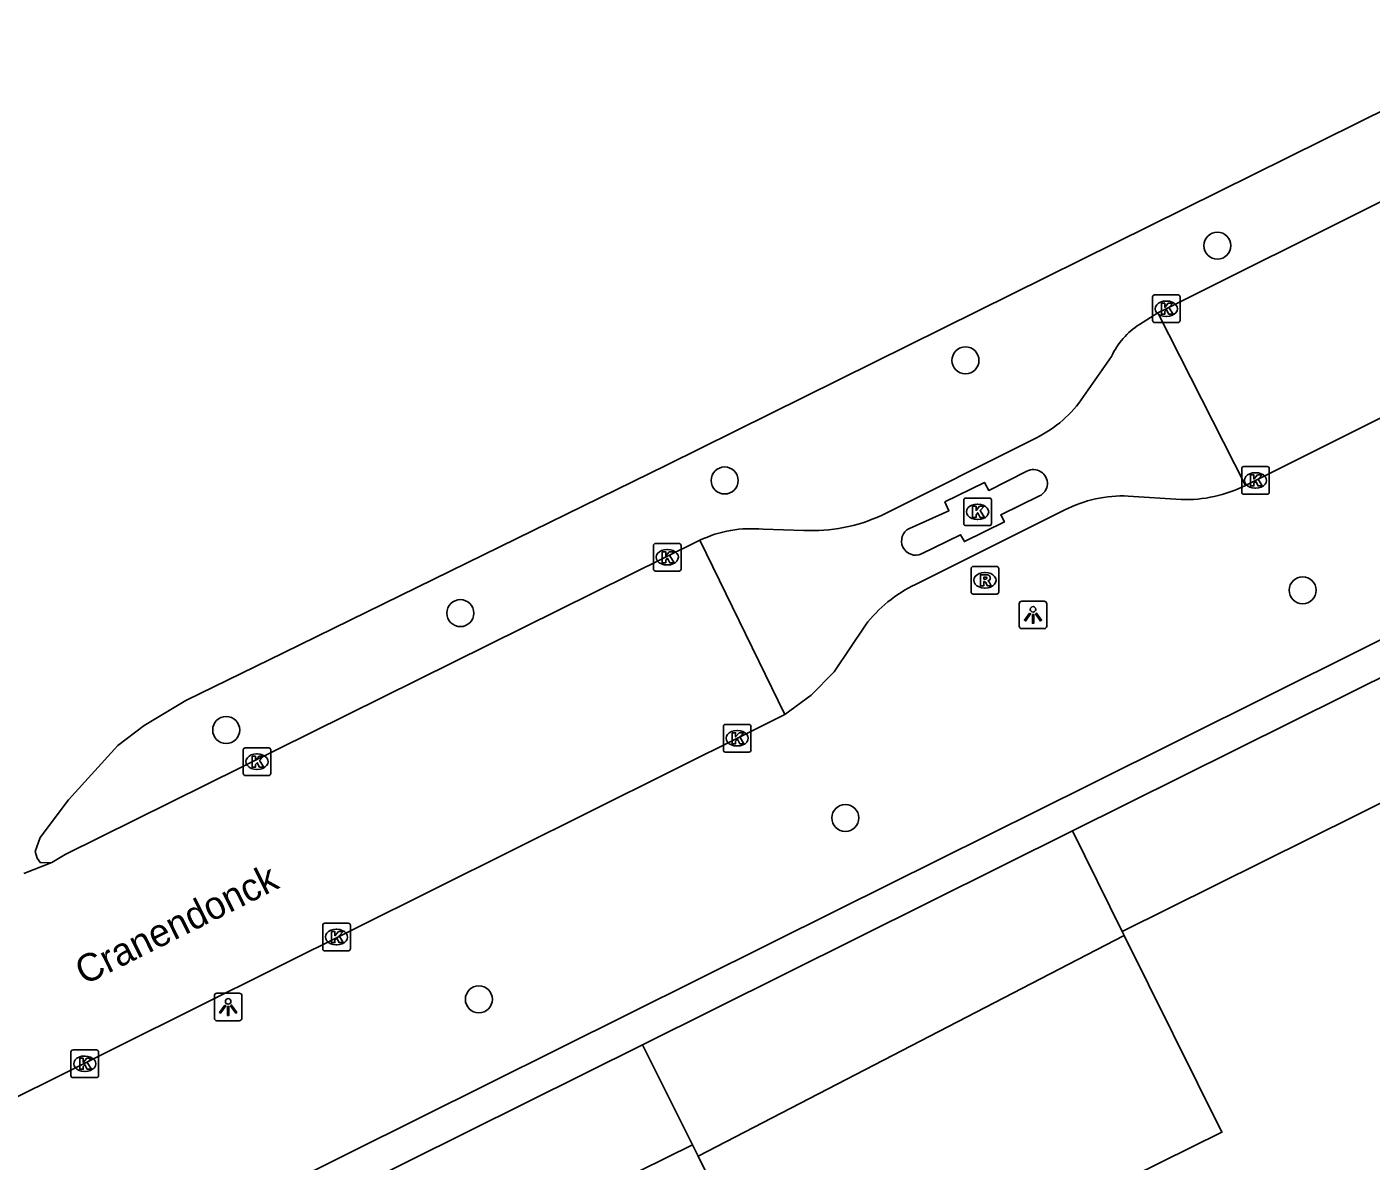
# Model space of a CAD drawing. Extents: x 157793 to 159380, y 380882 to 382313.
# Drawn here: x 157948.09 to 157996.75, y 381502.22 to 381543.27 of the extents above; entities that cross this region are included whole.
import ezdxf

# ---------------------------------------------------------------- set-up
doc = ezdxf.new("R2010")
doc.units = 0
for name, color, linetype in [('IMGEO_Boom', 7, 'Continuous'), ('IMGEO_Fietspad_gesloten', 7, 'Continuous'), ('IMGEO_Groenvoorziening', 7, 'Continuous'), ('IMGEO_Hek', 7, 'Continuous'), ('IMGEO_Kolk', 7, 'Continuous'), ('IMGEO_Lichtpunt', 7, 'Continuous'), ('IMGEO_Openbare_ruimte_label', 7, 'Continuous'), ('IMGEO_OVBaan_gesloten', 7, 'Continuous'), ('IMGEO_Pand', 7, 'Continuous'), ('IMGEO_Rioolput', 7, 'Continuous'), ('IMGEO_Voetpad_open', 7, 'Continuous')]:
    doc.layers.add(name, color=color, linetype=linetype)

msp = doc.modelspace()

# ---------------------------------------------------------------- linework, layer by layer
at = {"layer": 'IMGEO_Boom'}
for centre in [(157991.188, 381535.355), (157982.066, 381531.201), (157973.349, 381526.856), (157994.276, 381522.883), (157963.781, 381522.055), (157955.302, 381517.826), (157977.716, 381514.644), (157964.45, 381508.077)]:
    msp.add_circle(centre, 0.489, dxfattribs=at)
at = {"layer": 'IMGEO_Fietspad_gesloten'}
msp.add_lwpolyline([(157948.992, 381513.034), (157948.583, 381513.022), (157948.455, 381513.188), (157948.387, 381513.432), (157948.563, 381513.938), (157949.599, 381515.303), (157951.377, 381517.259), (157952.329, 381517.993), (157953.843, 381518.898), (157957.38, 381520.614), (157971.24, 381527.41), (158000, 381541.65), (158001.566, 381542.423), (158009.187, 381546.305), (158012.424, 381547.944)], dxfattribs=at)
at = {"layer": 'IMGEO_Groenvoorziening'}
for points in [[(157987.741, 381510.529), (157985.942, 381514.174)], [(157987.81, 381510.39), (157972.389, 381502.405)], [(157972.184, 381502.815), (157970.374, 381506.436)]]:
    msp.add_lwpolyline(points, dxfattribs=at)
at = {"layer": 'IMGEO_Hek'}
msp.add_lwpolyline([(157972.389, 381502.405), (157987.81, 381510.39)], dxfattribs=at)
at = {"layer": 'IMGEO_Kolk'}
for p, q in [((157988.837, 381532.644), (157988.837, 381533.496)), ((157988.912, 381533.57), (157989.764, 381533.57)), ((157989.325, 381533.35), (157989.35, 381533.35)), ((157989.838, 381533.496), (157989.838, 381532.644)), ((157989.348, 381532.79), (157989.323, 381532.79)), ((157989.764, 381532.57), (157988.912, 381532.57)), ((157992.066, 381526.432), (157992.066, 381527.284)), ((157992.141, 381527.358), (157992.993, 381527.358)), ((157993.067, 381527.284), (157993.067, 381526.432)), ((157992.554, 381527.138), (157992.579, 381527.138)), ((157992.993, 381526.358), (157992.141, 381526.358)), ((157992.577, 381526.578), (157992.552, 381526.578)), ((157982.005, 381525.295), (157982.005, 381526.147)), ((157982.08, 381526.221), (157982.932, 381526.221)), ((157982.493, 381526.001), (157982.518, 381526.001)), ((157983.006, 381526.147), (157983.006, 381525.295)), ((157982.516, 381525.441), (157982.491, 381525.441)), ((157982.932, 381525.221), (157982.08, 381525.221)), ((157970.77, 381523.651), (157970.77, 381524.503)), ((157970.845, 381524.577), (157971.697, 381524.577)), ((157971.258, 381524.357), (157971.283, 381524.357)), ((157971.771, 381524.503), (157971.771, 381523.651)), ((157971.697, 381523.577), (157970.845, 381523.577)), ((157971.281, 381523.797), (157971.256, 381523.797)), ((157973.376, 381518.027), (157974.228, 381518.027)), ((157973.301, 381517.101), (157973.301, 381517.953)), ((157973.789, 381517.807), (157973.814, 381517.807)), ((157974.302, 381517.953), (157974.302, 381517.101)), ((157955.917, 381516.252), (157955.917, 381517.104)), ((157955.992, 381517.178), (157956.844, 381517.178)), ((157956.918, 381517.104), (157956.918, 381516.252)), ((157973.812, 381517.247), (157973.787, 381517.247)), ((157956.405, 381516.958), (157956.43, 381516.958)), ((157974.228, 381517.027), (157973.376, 381517.027)), ((157956.844, 381516.178), (157955.992, 381516.178)), ((157956.428, 381516.398), (157956.403, 381516.398)), ((157958.796, 381509.907), (157958.796, 381510.759)), ((157958.871, 381510.833), (157959.723, 381510.833)), ((157959.797, 381510.759), (157959.797, 381509.907)), ((157959.284, 381510.613), (157959.309, 381510.613)), ((157959.723, 381509.833), (157958.871, 381509.833)), ((157959.307, 381510.053), (157959.282, 381510.053)), ((157949.681, 381505.319), (157949.681, 381506.171)), ((157949.756, 381506.245), (157950.608, 381506.245)), ((157950.169, 381506.025), (157950.194, 381506.025)), ((157950.682, 381506.171), (157950.682, 381505.319)), ((157950.192, 381505.465), (157950.167, 381505.465)), ((157950.608, 381505.245), (157949.756, 381505.245))]:
    msp.add_line(p, q, dxfattribs=at)
for points in [[(157988.837, 381532.644), (157988.837, 381533.496)], [(157988.912, 381533.57), (157989.764, 381533.57)], [(157989.158, 381533.27), (157989.281, 381533.27), (157989.281, 381533.119), (157989.411, 381533.27), (157989.575, 381533.27), (157989.429, 381533.119), (157989.582, 381532.87), (157989.43, 381532.87), (157989.345, 381533.034), (157989.281, 381532.967), (157989.281, 381532.87), (157989.158, 381532.87), (157989.158, 381533.27)], [(157989.838, 381533.496), (157989.838, 381532.644)], [(157989.764, 381532.57), (157988.912, 381532.57)], [(157992.066, 381526.432), (157992.066, 381527.284)], [(157992.141, 381527.358), (157992.993, 381527.358)], [(157993.067, 381527.284), (157993.067, 381526.432)], [(157992.387, 381527.058), (157992.51, 381527.058), (157992.51, 381526.907), (157992.64, 381527.058), (157992.804, 381527.058), (157992.658, 381526.907), (157992.811, 381526.658), (157992.659, 381526.658), (157992.574, 381526.822), (157992.51, 381526.755), (157992.51, 381526.658), (157992.387, 381526.658), (157992.387, 381527.058)], [(157992.993, 381526.358), (157992.141, 381526.358)], [(157982.005, 381525.295), (157982.005, 381526.147)], [(157982.08, 381526.221), (157982.932, 381526.221)], [(157982.326, 381525.921), (157982.449, 381525.921), (157982.449, 381525.77), (157982.579, 381525.921), (157982.743, 381525.921), (157982.597, 381525.77), (157982.75, 381525.521), (157982.598, 381525.521), (157982.513, 381525.685), (157982.449, 381525.618), (157982.449, 381525.521), (157982.326, 381525.521), (157982.326, 381525.921)], [(157983.006, 381526.147), (157983.006, 381525.295)], [(157982.932, 381525.221), (157982.08, 381525.221)], [(157970.77, 381523.651), (157970.77, 381524.503)], [(157970.845, 381524.577), (157971.697, 381524.577)], [(157971.771, 381524.503), (157971.771, 381523.651)], [(157971.091, 381524.277), (157971.214, 381524.277), (157971.214, 381524.126), (157971.344, 381524.277), (157971.508, 381524.277), (157971.362, 381524.126), (157971.515, 381523.877), (157971.363, 381523.877), (157971.278, 381524.041), (157971.214, 381523.974), (157971.214, 381523.877), (157971.091, 381523.877), (157971.091, 381524.277)], [(157971.697, 381523.577), (157970.845, 381523.577)], [(157973.376, 381518.027), (157974.228, 381518.027)], [(157973.301, 381517.101), (157973.301, 381517.953)], [(157973.622, 381517.727), (157973.745, 381517.727), (157973.745, 381517.576), (157973.875, 381517.727), (157974.039, 381517.727), (157973.893, 381517.576), (157974.046, 381517.327), (157973.894, 381517.327), (157973.809, 381517.491), (157973.745, 381517.424), (157973.745, 381517.327), (157973.622, 381517.327), (157973.622, 381517.727)], [(157974.302, 381517.953), (157974.302, 381517.101)], [(157955.917, 381516.252), (157955.917, 381517.104)], [(157955.992, 381517.178), (157956.844, 381517.178)], [(157956.918, 381517.104), (157956.918, 381516.252)], [(157956.238, 381516.878), (157956.361, 381516.878), (157956.361, 381516.727), (157956.491, 381516.878), (157956.655, 381516.878), (157956.509, 381516.727), (157956.662, 381516.478), (157956.51, 381516.478), (157956.425, 381516.642), (157956.361, 381516.575), (157956.361, 381516.478), (157956.238, 381516.478), (157956.238, 381516.878)], [(157974.228, 381517.027), (157973.376, 381517.027)], [(157956.844, 381516.178), (157955.992, 381516.178)], [(157958.796, 381509.907), (157958.796, 381510.759)], [(157958.871, 381510.833), (157959.723, 381510.833)], [(157959.797, 381510.759), (157959.797, 381509.907)], [(157959.117, 381510.533), (157959.24, 381510.533), (157959.24, 381510.382), (157959.37, 381510.533), (157959.534, 381510.533), (157959.388, 381510.382), (157959.541, 381510.133), (157959.389, 381510.133), (157959.304, 381510.297), (157959.24, 381510.23), (157959.24, 381510.133), (157959.117, 381510.133), (157959.117, 381510.533)], [(157959.723, 381509.833), (157958.871, 381509.833)], [(157949.681, 381505.319), (157949.681, 381506.171)], [(157949.756, 381506.245), (157950.608, 381506.245)], [(157950.002, 381505.945), (157950.125, 381505.945), (157950.125, 381505.794), (157950.255, 381505.945), (157950.419, 381505.945), (157950.273, 381505.794), (157950.426, 381505.545), (157950.274, 381505.545), (157950.189, 381505.709), (157950.125, 381505.642), (157950.125, 381505.545), (157950.002, 381505.545), (157950.002, 381505.945)], [(157950.682, 381506.171), (157950.682, 381505.319)], [(157950.608, 381505.245), (157949.756, 381505.245)]]:
    msp.add_lwpolyline(points, dxfattribs=at)
for centre, start, end in [((157988.914, 381533.494), 91.552, 178.448), ((157988.914, 381533.494), 91.552, 178.448), ((157989.762, 381533.494), 1.552, 88.448), ((157989.762, 381533.494), 1.552, 88.448), ((157988.914, 381532.646), 181.552, 268.448), ((157988.914, 381532.646), 181.552, 268.448), ((157989.762, 381532.646), 271.552, 358.448), ((157989.762, 381532.646), 271.552, 358.448), ((157992.143, 381527.282), 91.552, 178.448), ((157992.143, 381527.282), 91.552, 178.448), ((157992.991, 381527.282), 1.552, 88.448), ((157992.991, 381527.282), 1.552, 88.448), ((157992.143, 381526.434), 181.552, 268.448), ((157992.143, 381526.434), 181.552, 268.448), ((157992.991, 381526.434), 271.552, 358.448), ((157992.991, 381526.434), 271.552, 358.448), ((157982.082, 381526.145), 91.552, 178.448), ((157982.082, 381526.145), 91.552, 178.448), ((157982.93, 381526.145), 1.552, 88.448), ((157982.93, 381526.145), 1.552, 88.448), ((157982.082, 381525.297), 181.552, 268.448), ((157982.082, 381525.297), 181.552, 268.448), ((157982.93, 381525.297), 271.552, 358.448), ((157982.93, 381525.297), 271.552, 358.448), ((157970.847, 381524.501), 91.552, 178.448), ((157970.847, 381524.501), 91.552, 178.448), ((157971.695, 381524.501), 1.552, 88.448), ((157971.695, 381524.501), 1.552, 88.448), ((157970.847, 381523.653), 181.552, 268.448), ((157970.847, 381523.653), 181.552, 268.448), ((157971.695, 381523.653), 271.552, 358.448), ((157971.695, 381523.653), 271.552, 358.448), ((157973.378, 381517.951), 91.552, 178.448), ((157973.378, 381517.951), 91.552, 178.448), ((157974.226, 381517.951), 1.552, 88.448), ((157974.226, 381517.951), 1.552, 88.448), ((157955.994, 381517.102), 91.552, 178.448), ((157955.994, 381517.102), 91.552, 178.448), ((157956.842, 381517.102), 1.552, 88.448), ((157956.842, 381517.102), 1.552, 88.448), ((157973.378, 381517.103), 181.552, 268.448), ((157973.378, 381517.103), 181.552, 268.448), ((157974.226, 381517.103), 271.552, 358.448), ((157974.226, 381517.103), 271.552, 358.448), ((157955.994, 381516.254), 181.552, 268.448), ((157955.994, 381516.254), 181.552, 268.448), ((157956.842, 381516.254), 271.552, 358.448), ((157956.842, 381516.254), 271.552, 358.448), ((157958.873, 381510.757), 91.552, 178.448), ((157958.873, 381510.757), 91.552, 178.448), ((157959.721, 381510.757), 1.552, 88.448), ((157959.721, 381510.757), 1.552, 88.448), ((157958.873, 381509.909), 181.552, 268.448), ((157958.873, 381509.909), 181.552, 268.448), ((157959.721, 381509.909), 271.552, 358.448), ((157959.721, 381509.909), 271.552, 358.448), ((157949.758, 381506.169), 91.552, 178.448), ((157949.758, 381506.169), 91.552, 178.448), ((157950.606, 381506.169), 1.552, 88.448), ((157950.606, 381506.169), 1.552, 88.448), ((157949.758, 381505.321), 181.552, 268.448), ((157949.758, 381505.321), 181.552, 268.448), ((157950.606, 381505.321), 271.552, 358.448), ((157950.606, 381505.321), 271.552, 358.448)]:
    msp.add_arc(centre, 0.0765, start, end, dxfattribs=at)
for centre, major_axis, ratio, start_param, end_param in [((157989.324, 381533.07), (-0.387, 0.002), 0.722429, 4.712389, 7.853982), ((157989.349, 381533.07), (-0.39, 0.002), 0.717154, 1.570796, 4.712389), ((157992.553, 381526.858), (-0.387, 0.002), 0.722429, 4.712389, 7.853982), ((157992.578, 381526.858), (-0.39, 0.002), 0.717154, 1.570796, 4.712389), ((157982.492, 381525.721), (-0.387, 0.002), 0.722429, 4.712389, 7.853982), ((157982.517, 381525.721), (-0.39, 0.002), 0.717154, 1.570796, 4.712389), ((157971.257, 381524.077), (-0.387, 0.002), 0.722429, 4.712389, 7.853982), ((157971.282, 381524.077), (-0.39, 0.002), 0.717154, 1.570796, 4.712389), ((157973.788, 381517.527), (-0.387, 0.002), 0.722429, 4.712389, 7.853982), ((157973.813, 381517.527), (-0.39, 0.002), 0.717154, 1.570796, 4.712389), ((157956.404, 381516.678), (-0.387, 0.002), 0.722429, 4.712389, 7.853982), ((157956.429, 381516.678), (-0.39, 0.002), 0.717154, 1.570796, 4.712389), ((157959.283, 381510.333), (-0.387, 0.002), 0.722429, 4.712389, 7.853982), ((157959.308, 381510.333), (-0.39, 0.002), 0.717154, 1.570796, 4.712389), ((157950.168, 381505.745), (-0.387, 0.002), 0.722429, 4.712389, 7.853982), ((157950.193, 381505.745), (-0.39, 0.002), 0.717154, 1.570796, 4.712389)]:
    msp.add_ellipse(centre, major_axis=major_axis, ratio=ratio, start_param=start_param, end_param=end_param, dxfattribs=at)
at = {"layer": 'IMGEO_Lichtpunt'}
for p, q in [((157984.013, 381522.394), (157984.013, 381521.587)), ((157984.013, 381522.394), (157984.013, 381521.587)), ((157984.915, 381522.489), (157984.107, 381522.489)), ((157984.915, 381522.489), (157984.107, 381522.489)), ((157985.009, 381521.587), (157985.009, 381522.394)), ((157985.009, 381521.587), (157985.009, 381522.394)), ((157984.107, 381521.493), (157984.915, 381521.493)), ((157984.107, 381521.493), (157984.915, 381521.493)), ((157955.777, 381508.3), (157954.969, 381508.3)), ((157955.777, 381508.3), (157954.969, 381508.3)), ((157954.875, 381508.205), (157954.875, 381507.398)), ((157954.875, 381508.205), (157954.875, 381507.398)), ((157955.871, 381507.398), (157955.871, 381508.205)), ((157955.871, 381507.398), (157955.871, 381508.205)), ((157954.969, 381507.304), (157955.777, 381507.304)), ((157954.969, 381507.304), (157955.777, 381507.304))]:
    msp.add_line(p, q, dxfattribs=at)
for points in [[(157984.387, 381522.058), (157984.426, 381522.03), (157984.238, 381521.768), (157984.2, 381521.795), (157984.387, 381522.058)], [(157984.489, 381522.01), (157984.536, 381522.01), (157984.536, 381521.688), (157984.489, 381521.688), (157984.489, 381522.01)], [(157984.599, 381522.03), (157984.637, 381522.057), (157984.824, 381521.795), (157984.785, 381521.767), (157984.599, 381522.03)], [(157955.249, 381507.869), (157955.288, 381507.841), (157955.1, 381507.579), (157955.062, 381507.606), (157955.249, 381507.869)], [(157955.351, 381507.821), (157955.398, 381507.821), (157955.398, 381507.499), (157955.351, 381507.499), (157955.351, 381507.821)], [(157955.461, 381507.841), (157955.499, 381507.868), (157955.686, 381507.606), (157955.647, 381507.578), (157955.461, 381507.841)]]:
    msp.add_lwpolyline(points, dxfattribs=at)
for centre in [(157984.512, 381522.192), (157955.374, 381508.003)]:
    msp.add_circle(centre, 0.0994, dxfattribs=at)
for centre, start, end in [((157984.107, 381522.394), 90, 180), ((157984.107, 381522.394), 90, 180), ((157984.915, 381522.394), 0, 90), ((157984.915, 381522.394), 0, 90), ((157984.107, 381521.587), 180, 270), ((157984.107, 381521.587), 180, 270), ((157984.915, 381521.587), 270, 0), ((157984.915, 381521.587), 270, 360), ((157954.969, 381508.205), 90, 180), ((157954.969, 381508.205), 90, 180), ((157955.777, 381508.205), 0, 90), ((157955.777, 381508.205), 0, 90), ((157954.969, 381507.398), 180, 270), ((157954.969, 381507.398), 180, 270), ((157955.777, 381507.398), 270, 0), ((157955.777, 381507.398), 270, 360)]:
    msp.add_arc(centre, 0.0946, start, end, dxfattribs=at)
at = {"layer": 'IMGEO_OVBaan_gesloten'}
for points in [[(157989.033, 381532.928), (157989.337, 381533.071), (157997.095, 381536.942), (158000, 381538.05), (158006.762, 381540.629)], [(157988.366, 381532.506), (157989.033, 381532.928)], [(157992.209, 381526.676), (157989.033, 381532.928)], [(158003.273, 381531.785), (158000, 381530.433), (157999.312, 381530.149), (157997.534, 381529.339), (157993.15, 381527.148), (157992.568, 381526.857), (157992.209, 381526.676)], [(157986.258, 381529.773), (157987.354, 381531.346)], [(157979.024, 381525.593), (157984.513, 381528.343)], [(157984.29, 381527.187), (157982.907, 381526.494), (157982.751, 381526.783), (157981.321, 381526.08), (157981.465, 381525.759), (157980.036, 381525.123)], [(157980.473, 381524.196), (157981.891, 381524.893), (157982.027, 381524.646), (157983.477, 381525.356), (157983.344, 381525.611), (157984.748, 381526.296)], [(157989.875, 381526.167), (157987.958, 381526.293)], [(157985.661, 381525.788), (157980.254, 381523.091)], [(157974.737, 381525.088), (157976.215, 381525.049)], [(157948.992, 381513.034), (157949.467, 381513.314), (157972.452, 381524.691)], [(157972.452, 381524.691), (157975.532, 381518.391)], [(157978.442, 381521.621), (157977.311, 381519.933), (157976.482, 381519.092), (157975.532, 381518.391)], [(157975.532, 381518.391), (157974.242, 381517.749), (157951.365, 381506.36), (157945.482, 381503.431), (157943.15, 381502.27)], [(157947.975, 381512.633), (157948.992, 381513.034)]]:
    msp.add_lwpolyline(points, dxfattribs=at)
for centre, radius, start, end in [((157989.892, 381530.153), 2.804, 122.9655, 154.8307), ((157982.643, 381532.405), 4.472, 294.7222, 323.9459), ((157984.533, 381526.749), 0.501, 295.3673, 119.0417), ((157987.77, 381521.673), 4.624, 87.6675, 117.1311), ((157990.029, 381531.065), 4.901, 268.1957, 296.4092), ((157976.532, 381530.936), 5.895, 266.9163, 295.0045), ((157974.296, 381520.851), 4.26, 84.0604, 115.6522), ((157980.265, 381524.664), 0.513, 116.5033, 293.9763), ((157982.446, 381518.537), 5.054, 115.7043, 142.3977)]:
    msp.add_arc(centre, radius, start, end, dxfattribs=at)
at = {"layer": 'IMGEO_Pand'}
for points in [[(157999.625, 381516.436), (157987.741, 381510.529)], [(157987.81, 381510.39), (157991.351, 381503.266), (157984.739, 381500), (157975.794, 381495.582), (157973.589, 381500), (157972.389, 381502.405)], [(157987.741, 381510.529), (157987.81, 381510.39)], [(157960.246, 381496.977), (157960.095, 381497.313), (157960.525, 381497.527), (157960.717, 381497.143), (157966.493, 381500), (157972.184, 381502.815)], [(157972.389, 381502.405), (157972.184, 381502.815)]]:
    msp.add_lwpolyline(points, dxfattribs=at)
at = {"layer": 'IMGEO_Rioolput'}
for p, q in [((157982.271, 381522.817), (157982.271, 381523.669)), ((157982.346, 381523.743), (157983.198, 381523.743)), ((157982.759, 381523.523), (157982.784, 381523.523)), ((157983.272, 381523.669), (157983.272, 381522.817)), ((157982.782, 381522.963), (157982.757, 381522.963)), ((157983.198, 381522.743), (157982.346, 381522.743))]:
    msp.add_line(p, q, dxfattribs=at)
for points in [[(157982.271, 381522.817), (157982.271, 381523.669)], [(157982.346, 381523.743), (157983.198, 381523.743)], [(157982.86, 381523.441), (157982.608, 381523.443), (157982.608, 381523.043)], [(157982.786, 381523.362), (157982.732, 381523.362), (157982.732, 381523.281)], [(157983.272, 381523.669), (157983.272, 381522.817)], [(157982.608, 381523.043), (157982.732, 381523.043), (157982.732, 381523.205), (157982.743, 381523.205)], [(157982.732, 381523.281), (157982.784, 381523.281)], [(157982.79, 381523.176), (157982.861, 381523.043), (157983.001, 381523.043), (157982.936, 381523.169)], [(157983.198, 381522.743), (157982.346, 381522.743)]]:
    msp.add_lwpolyline(points, dxfattribs=at)
for centre, radius, start, end in [((157982.348, 381523.667), 0.0765, 91.552, 178.448), ((157982.348, 381523.667), 0.0765, 91.552, 178.448), ((157982.792, 381523.266), 0.0964, 77.0061, 93.1865), ((157982.859, 381523.331), 0.109, 350.3612, 89.416), ((157983.196, 381523.667), 0.0765, 1.552, 88.448), ((157983.196, 381523.667), 0.0765, 1.552, 88.448), ((157982.742, 381523.152), 0.0533, 26.0293, 88.6989), ((157982.768, 381523.47), 0.19, 274.7715, 282.9687), ((157982.806, 381523.323), 0.0378, 276.6634, 79.6772), ((157982.857, 381523.331), 0.112, 277.5842, 350.9817), ((157982.841, 381523.116), 0.108, 29.5134, 73.7905), ((157982.348, 381522.819), 0.0765, 181.552, 268.448), ((157982.348, 381522.819), 0.0765, 181.552, 268.448), ((157983.196, 381522.819), 0.0765, 271.552, 358.448), ((157983.196, 381522.819), 0.0765, 271.552, 358.448)]:
    msp.add_arc(centre, radius, start, end, dxfattribs=at)
for centre, major_axis, ratio, start_param, end_param in [((157982.758, 381523.243), (-0.387, 0.002), 0.722429, 4.712389, 7.853982), ((157982.783, 381523.243), (-0.39, 0.002), 0.717154, 1.570796, 4.712389)]:
    msp.add_ellipse(centre, major_axis=major_axis, ratio=ratio, start_param=start_param, end_param=end_param, dxfattribs=at)
at = {"layer": 'IMGEO_Voetpad_open'}
for points in [[(157954.478, 381499.89), (157954.701, 381500), (157977.445, 381511.314), (157986.551, 381515.844), (157996.349, 381520.716), (158000, 381522.532), (158018.563, 381531.762), (158016.931, 381535.529), (158003.906, 381530.411), (158003.273, 381531.785)], [(157997.811, 381520.074), (157985.942, 381514.174)], [(157985.942, 381514.174), (157970.374, 381506.436)], [(157970.374, 381506.436), (157957.674, 381500.123), (157957.427, 381500), (157955.015, 381498.801), (157954.478, 381499.89)]]:
    msp.add_lwpolyline(points, dxfattribs=at)

# ---------------------------------------------------------------- texts
at = {"layer": 'IMGEO_Openbare_ruimte_label'}
msp.add_text('Cranendonck', height=1, rotation=26.4882, dxfattribs=at).set_placement((157950.159, 381508.579))

doc.saveas('drawing.dxf')
